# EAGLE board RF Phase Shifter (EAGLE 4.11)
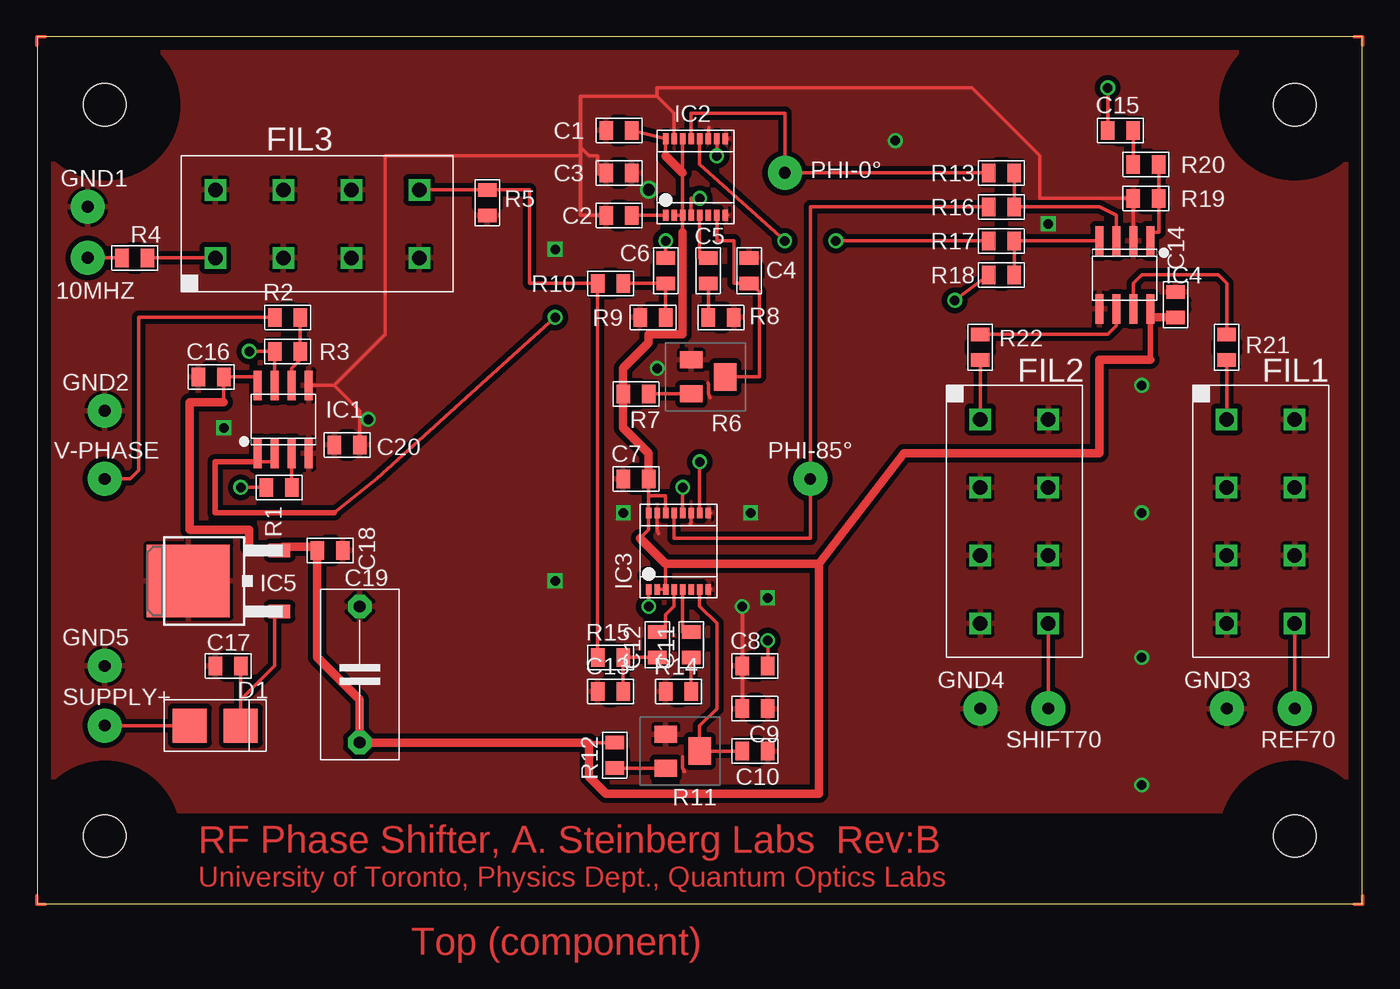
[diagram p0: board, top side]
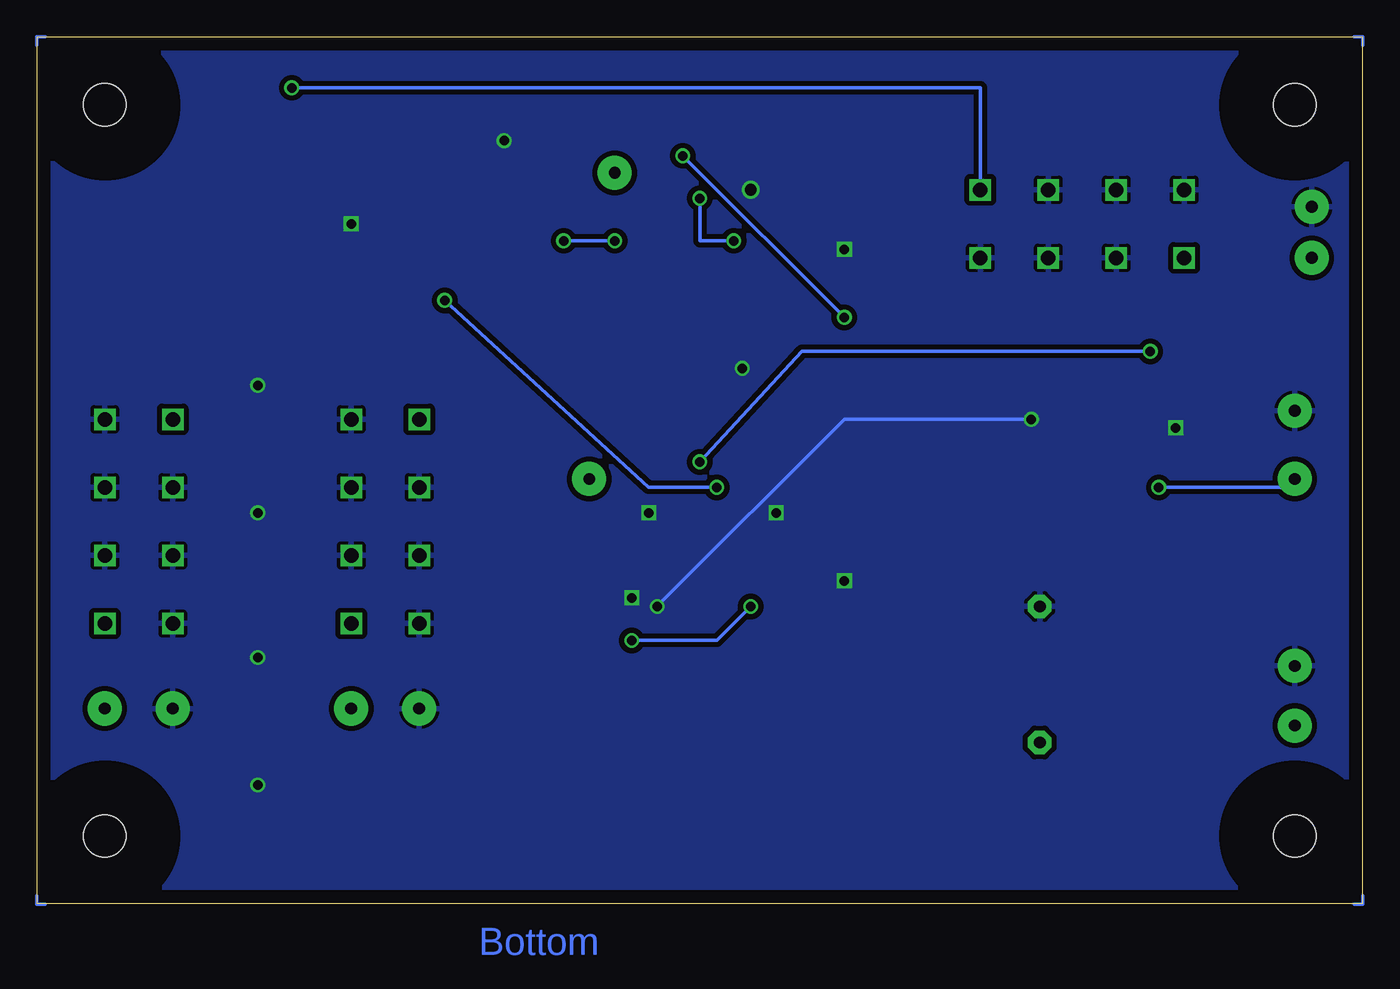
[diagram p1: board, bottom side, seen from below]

Size 99.04 x 64.76 mm. Coordinates in mm from the lower left corner, seen from the top.
Outline: 34.92,0.01 99.04,0.01
Outline: 0,0 99.03,0 99.03,64.76 0,64.76 0,0
Copper layers (1*16): Top 0.035mm / dielectric 1.5mm / Bottom 0.035mm
Design rules "default": minimum track width 10mil, minimum drill 24mil, track to track 12mil, track to pad 10mil, pad to pad 8mil, via to via 10mil, smd to smd 8mil, copper to edge 40mil, drill to drill 8mil, minimum pad ring 10mil, minimum via ring 8mil, stop-mask expansion 4mil, vias tented up to drill 0mil, thermal gap 10mil
Holes 3.17 mm at 5.07,5.08 93.97,5.08 5.07,59.68 93.97,59.68
tKeepout: area -0.2,-0.2 to 10.3,10.3; area 88.7,-0.2 to 99.2,10.3; area -0.2,54.4 to 10.3,64.9; area 88.7,54.4 to 99.2,64.9
tRestrict: area -0.2,54.4 to 10.3,64.9; area 88.7,54.4 to 99.2,64.9; area -0.2,-0.2 to 10.3,10.3; area 88.7,-0.2 to 99.2,10.3
bRestrict: area -0.2,-0.2 to 10.3,10.3; area 88.7,-0.2 to 99.2,10.3; area 88.7,54.4 to 99.2,64.9; area -0.2,54.4 to 10.3,64.9

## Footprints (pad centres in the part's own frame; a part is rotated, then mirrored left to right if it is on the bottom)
TP-HOLE = drill 0.889 pad 2.54 round: P$1 0,0
0805 = smd 1.016 x 1.397: 1 -1.905,0; 2 0,0
PASSIVE_0.4" = drill 0.889 pad 1.778 octagon: 1 -5.08,0; 2 5.08,0
DIODE-SMT = smd 2.54 x 2.54: A -1.27,0; K 2.54,0
A01-MINICIRCUITS = drill 1.067 square: 1 -7.62,-2.54; 2 -7.62,2.54; 3 -2.54,-2.54; 4 -2.54,2.54; 5 2.54,-2.54; 6 2.54,2.54; 7 7.62,-2.54; 8 7.62,2.54
SOIC8 = smd 0.6 x 2.2: 1 -1.905,-2.54; 2 -0.635,-2.54; 3 0.635,-2.54; 4 1.905,-2.54; 5 1.905,2.54; 6 0.635,2.54; 7 -0.635,2.54; 8 -1.905,2.54
QSOP-16(RQ-16) = smd 0.406 x 0.813: 1 -1.27,-3.175; 2 -0.635,-3.175; 3 0,-3.175; 4 0.635,-3.175; 5 1.27,-3.175; 6 1.905,-3.175; 7 2.54,-3.175; 8 3.175,-3.175; 9 3.175,2.54; 10 2.54,2.54; 11 1.905,2.54; 12 1.27,2.54; 13 0.635,2.54; 14 0,2.54; 15 -0.635,2.54; 16 -1.27,2.54
TO252 = smd 1 x 1.6: 1 -2.28,-4.8; 2 2.28,-4.8 | smd 5.4 x 6.2: 3 0,2.02
3214W = smd 1.651 x 1.27: CCW 1.27,-1.27; CW 1.27,1.27 | smd 1.651 x 2.032: W -1.27,0

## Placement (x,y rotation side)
10MHZ  [TP-HOLE]  3.8,48.25 0 top
C1  0.1uF  [0805]  44.44,57.78 0 top
C2  330pF  [0805]  44.44,51.43 0 top
C3  0.1uF  [0805]  42.53,54.6 180 top
C4  0.1uF  [0805]  53.2,46.35 270 top
C5  330pF  [0805]  50.15,48.25 90 top
C6  330pF  [0805]  46.98,48.25 90 top
C7  0.1uF  [0805]  45.71,31.75 0 top
C8  330pF  [0805]  54.6,17.78 0 top
C9  0.1uF  [0805]  52.69,14.6 180 top
C10  0.1uF  [0805]  52.69,11.42 180 top
C11  330pF  [0805]  48.88,20.32 90 top
C12  330pF  [0805]  46.34,20.32 90 top
C13  330pF  [0805]  43.8,15.87 0 top
C14  0.1uF  [0805]  85.08,45.71 90 top
C15  330pF  [0805]  81.9,57.78 0 top
C16  0.1uF  [0805]  13.96,39.36 0 top
C17  0.1uF  [0805]  15.23,17.78 0 top
C18  0.1uF  [0805]  20.94,26.41 180 top
C19  10uF  [PASSIVE_0.4"]  24.12,17.14 270 top
C20  0.1uF  [0805]  24.12,34.28 0 top
D1  1N4004  [DIODE-SMT]  12.69,13.33 0 top
FIL1  PBP-70  [A01-MINICIRCUITS]  91.43,28.57 270 top
FIL2  PBP-70  [A01-MINICIRCUITS]  73.01,28.57 270 top
FIL3  PLP10.7  [A01-MINICIRCUITS]  20.94,50.79 0 top
GND1  [TP-HOLE]  3.8,52.06 0 top
GND2  [TP-HOLE]  5.07,36.82 0 top
GND3  [TP-HOLE]  88.89,14.6 0 top
GND4  [TP-HOLE]  70.47,14.6 0 top
GND5  [TP-HOLE]  5.07,17.78 0 top
IC1  LT1807CS8  [SOIC8]  18.4,36.19 0 top
IC2  AD8330ARQ  [QSOP-16(RQ-16)]  48.25,54.6 0 top
IC3  AD8330ARQ  [QSOP-16(RQ-16)]  46.98,26.67 0 top
IC4  LT1720  [SOIC8]  81.27,46.98 180 top
IC5  7805DT  [TO252]  13.32,24.12 90 top
PHI-0°  [TP-HOLE]  55.87,54.6 90 top
PHI-85°  [TP-HOLE]  57.77,31.75 0 top
R1  2.21K  [0805]  19.04,31.11 0 top
R2  2.21K  [0805]  19.67,43.81 0 top
R3  2.21K  [0805]  17.77,41.27 180 top
R4  49.9  [0805]  8.24,48.25 0 top
R5  64.9  [0805]  33.64,53.34 90 top
R6  10K  [3214W]  50.15,39.36 180 top
R7  2.21K  [0805]  43.8,38.09 180 top
R8  49.9  [0805]  50.15,43.81 180 top
R9  49.9  [0805]  46.98,43.81 0 top
R10  499  [0805]  43.8,46.35 0 top
R11  10K  [3214W]  48.25,11.42 180 top
R12  2.21K  [0805]  43.17,12.06 90 top
R13  221  [0805]  71.11,54.6 180 top
R14  49.9  [0805]  48.88,15.87 0 top
R15  499  [0805]  43.8,18.41 0 top
R16  221  [0805]  73.01,52.06 0 top
R17  221  [0805]  71.11,49.52 180 top
R18  221  [0805]  73.01,46.98 0 top
R19  2.21K  [0805]  83.81,52.7 0 top
R20  499  [0805]  83.81,55.24 0 top
R21  49.9  [0805]  88.89,40.63 270 top
R22  49.9  [0805]  70.47,40.63 270 top
REF70  [TP-HOLE]  93.97,14.6 0 top
SHIFT70  [TP-HOLE]  75.55,14.6 0 top
SUPPLY+  [TP-HOLE]  5.07,13.33 0 top
U$26  [TARGET]  not placed on the board
U$27  [TARGET]  not placed on the board
U$28  [TARGET]  not placed on the board
U$29  [TITLEBLOCK_PCB]  not placed on the board
V-PHASE  [TP-HOLE]  5.07,31.75 0 top

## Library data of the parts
10MHZ C1-C20 D1 FIL1-FIL3 GND1-GND5 IC1-IC5 PHI-0° PHI-85° R1-R22 REF70 SHIFT70 SUPPLY+ U$26-U$29 V-PHASE = 0-UofT-Physics

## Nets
+2.5V: C1.1 C2.1 C3.1 C3.2 C4.1 C7.1 C8.1 C9.1 C9.2 C10.1 C13.1 C14.2 C16.1 C17.1 C18.1 C19.1 C20.1 C20.2 FIL1.2 FIL1.3 FIL1.4 FIL1.5 FIL1.6 FIL1.7 FIL2.2 FIL2.3 FIL2.4 FIL2.5 FIL2.6 FIL2.7 FIL3.2 FIL3.3 FIL3.4 FIL3.5 FIL3.6 FIL3.7 GND1.P$1 GND2.P$1 GND3.P$1 GND4.P$1 GND5.P$1 IC1.4 IC1.5 IC2.8 IC2.9 IC2.11 IC2.15 IC3.8 IC3.9 IC3.11 IC3.15 IC4.2 IC4.5 IC5.3 R5.1 R6.CCW R8.1 R9.1 R11.CCW R14.1 R19.1
+5V: C1.2 C7.2 C14.1 C16.2 C18.2 C19.2 IC1.8 IC2.2 IC2.3 IC2.14 IC2.16 IC3.2 IC3.3 IC3.14 IC3.16 IC4.8 IC5.2 R7.2 R12.2
N$1: IC1.1 IC1.2 IC2.10
N$2: IC1.3 R1.2
N$3: R1.1 R2.1 V-PHASE.P$1
N$4: D1.A SUPPLY+.P$1
N$5: IC1.7 IC3.10 R3.2
N$6: C12.1 C13.2 R15.2
N$7: 10MHZ.P$1 R4.1
N$8: IC1.6 R2.2 R3.1
N$9: FIL3.1 R4.2
N$10: R11.CW R12.1
N$11: IC2.12 R17.2
N$12: C2.2 IC2.1
N$13: C4.2 IC2.7 R6.W
N$14: R6.CW R7.1
N$15: IC2.13 PHI-0°.P$1 R13.2
N$16: C6.1 R9.2 R10.2
N$17: C5.1 R8.2
N$18: C5.2 IC2.5
N$19: C6.2 IC2.4
N$20: IC4.4 R17.1 R18.2
N$21: IC4.3 R13.1 R16.2
N$22: C8.2 IC3.1
N$23: C10.2 IC3.7 R11.W
N$24: IC3.12 R18.1
N$25: C11.1 R14.2
N$26: C11.2 IC3.5
N$27: C12.2 IC3.4
N$29: IC3.13 PHI-85°.P$1 R16.1
N$30: IC4.7 R21.1
N$31: IC4.1 R19.2 R20.2
N$32: C15.2 R20.1
N$33: FIL2.1 R22.2
N$34: FIL1.1 R21.2
N$35: IC4.6 R22.1
N$36: FIL1.8 REF70.P$1
N$37: FIL2.8 SHIFT70.P$1
N$38: C15.1 FIL3.8 R5.2 R10.1 R15.1
N$39: C17.2 D1.K IC5.1

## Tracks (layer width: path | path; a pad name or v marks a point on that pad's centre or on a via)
+2.5V  (via drill 0.71, 0.89)
  Top 0.254: IC4.2 R19.1 74.92,52.7 74.92,55.88 69.84,60.95 46.34,60.95 46.34,60.32 | C9.2 C8.1 v52.69,22.22 | IC2.15 47.61,59.05 46.34,60.32 | 46.34,60.32 40.63,60.32 40.63,56.51 | 40.63,56.51 41.26,55.88 41.9,55.88 41.9,54.6 42.53,53.97 C3.2 | C2.1 40.63,51.43 40.63,55.88 | 40.63,55.88 40.63,56.51 | 24.12,36.19 24.12,36.82 22.21,38.73 | 22.21,38.73 IC1.5 | C20.2 24.12,36.19 | 24.12,36.19 v24.75,36.19 | 40.63,55.88 26.02,55.88 26.02,42.54 22.21,38.73 | IC3.15 46.34,27.94 46.42,27.64 | 50.18,23.49 IC3.8 50.3,23.49 | 48.25,10.15 48.25,10.79 48.23,11 | 48.25,10.15 48.26,10.15 | 50.18,29.2 IC3.9 50.3,29.2 | 51.45,51.43 IC2.8 51.57,51.43 | IC2.11 50.15,57.78 50.22,58.01 | 51.45,57.14 IC2.9 51.57,57.14 | 50.15,38.09 50.15,38.73 50.14,38.95 | 50.15,38.09 50.17,38.09 | 48.39,9.89 48.25,10.15 | 50.29,37.83 50.15,38.09 | IC3.11 48.88,28.57 48.82,28.34
  Bottom 0.254: v52.69,22.22 38.72,36.19 v24.75,36.19
  other vias: 46.34,40 45.71,53.34 64.12,57.02 82.54,38.73 82.54,29.21 82.54,18.41 82.54,8.88 43.8,29.21 53.33,29.21 54.6,22.86 38.72,24.12 13.96,35.55 38.72,48.89 75.55,50.79
  pour Bottom (isolate 0.381): 0.62,0.5 98.41,0.5 98.41,64.13 0.62,64.13
  pour Top (isolate 0.381): 0.62,6.98 98.41,6.98 98.41,64.13 0.62,64.13
+5V
  Top 0.254: IC1.8 16.5,39.36 C16.2 13.96,37.46 | 15.86,26.67 17.77,26.67 IC5.2 18.4,26.67 | 41.26,12.06 R12.2 | C1.2 IC2.16 46.98,55.88 | IC2.3 IC2.2 | IC2.3 48.25,54.6 IC2.14 | IC3.2 IC3.3 46.98,25.39 | 45.07,27.3 45.71,27.94 IC3.16 45.71,30.48 | 48.25,50.16 IC2.3 | IC3.14 46.98,30.48 45.71,30.48 | 45.71,30.48 C7.2 | C18.2 20.94,26.67 | 83.17,43.81 IC4.8
  Top 0.406: 83.17,40.63 83.17,43.81
  Top 0.635: 48.25,54.6 46.98,55.88 | 45.07,27.3 46.98,25.39 58.41,25.39 | 58.41,25.39 64.76,33.65 79.36,33.65 79.36,40.63 83.17,40.63 | 58.41,25.39 58.41,8.25 42.53,8.25 41.26,9.52 41.26,12.06 C19.2 24.12,15.23 20.94,18.41 C18.2 | C7.2 45.71,33.65 43.8,35.55 R7.2 43.8,40 45.71,41.9 45.71,42.54 48.25,42.54 48.25,50.16 | 20.94,26.67 18.4,26.67 | 15.86,26.67 15.86,27.94 11.42,27.94 11.42,37.46 13.96,37.46 | 83.17,43.81 C14.1
N$1  (via drill 0.71)
  Top 0.254: v50.79,55.88 IC2.10 | v38.72,43.81 25.39,31.75 22.21,29.21 | IC1.2 17.77,33.02 16.5,33.02 IC1.1
  Top 0.406: 22.21,29.21 13.32,29.21 13.32,33.02 16.5,33.02
  Bottom 0.254: v38.72,43.81 v50.79,55.88
N$2
  Top 0.254: R1.2 IC1.3
N$3  (via drill 0.71)
  Top 0.254: v15.23,31.11 R1.1 | R2.1 7.61,43.81 7.61,32.38 6.97,31.75 V-PHASE.P$1
  Bottom 0.254: v15.23,31.11 5.7,31.11 V-PHASE.P$1
N$4
  Top 0.254: SUPPLY+.P$1 D1.A
N$5  (via drill 0.71)
  Top 0.254: v49.52,33.02 IC3.10 | v15.86,41.27 R3.2 IC1.7
  Bottom 0.254: v49.52,33.02 41.9,41.27 v15.86,41.27
N$6
  Top 0.254: C13.2 R15.2 C12.1
N$7
  Top 0.254: 10MHZ.P$1 R4.1
N$8
  Top 0.254: R2.2 R3.1 19.67,40.63 19.04,40 IC1.6
N$9
  Top 0.254: R4.2 FIL3.1
N$10
  Top 0.254: R12.1 R11.CW
N$11  (via drill 0.71)
  Top 0.254: IC2.12 49.52,55.24 v55.87,49.52 | v59.68,49.52 R17.2
  Bottom 0.254: v55.87,49.52 v59.68,49.52
N$12
  Top 0.254: C2.2 IC2.1
N$13
  Top 0.254: 52.06,40 R6.W 53.96,39.36 53.96,45.71 53.33,46.35 C4.2 52.06,46.35 52.06,49.52 50.79,49.52 IC2.7
N$14
  Top 0.254: R7.1 R6.CW
N$15
  Top 0.254: IC2.13 48.88,59.05 55.87,59.05 PHI-0°.P$1 R13.2
N$16
  Top 0.254: R10.2 C6.1 R9.2
N$17
  Top 0.254: R8.2 C5.1
N$18
  Top 0.254: IC2.5 49.52,48.25 C5.2
N$19  (via drill 0.71)
  Top 0.254: IC2.4 48.88,52.7 v49.52,52.7 | C6.2 v46.98,49.52
  Bottom 0.254: v49.52,52.7 49.52,49.52 v46.98,49.52
N$20
  Top 0.254: R18.2 R17.1 IC4.4
N$21
  Top 0.254: R13.1 R16.2 79.36,52.06 80.63,51.43 IC4.3
N$22  (via drill 0.71)
  Top 0.254: v45.71,22.22 IC3.1 | v54.6,19.68 C8.2
  Bottom 0.254: v45.71,22.22 48.25,19.68 v54.6,19.68
N$23
  Top 0.254: IC3.7 49.52,22.22 50.79,20.95 50.79,14.6 49.52,13.33 R11.W C10.2
N$24  (via drill 0.71)
  Top 0.254: IC3.12 v48.25,31.11 | v68.57,45.08 R18.1
  Bottom 0.254: v48.25,31.11 53.33,31.11 v68.57,45.08
N$25
  Top 0.254: R14.2 C11.1
N$26
  Top 0.254: IC3.5 48.25,20.32 C11.2
N$27
  Top 0.254: IC3.4 47.61,22.22 46.98,21.59 46.98,20.32 C12.2
N$28
  Bottom 0.254: -0.01,0.63 -0.01,-0.01 0.62,-0.01
N$29
  Top 0.254: IC3.13 47.61,27.3 57.77,27.3 PHI-85°.P$1 57.77,52.06 R16.1
N$30
  Top 0.254: R21.1 88.89,46.35 88.25,46.98 82.54,46.98 81.9,46.35 IC4.7
N$31
  Top 0.254: IC4.1 83.17,50.16 83.81,50.16 R19.2 R20.2
N$32
  Top 0.254: R20.1 C15.2
N$33
  Top 0.254: FIL2.1 R22.2
N$34
  Top 0.254: FIL1.1 R21.2
N$35
  Top 0.254: R22.1 80,42.54 80.63,43.17 IC4.6
N$36
  Top 0.254: REF70.P$1 FIL1.8
N$37
  Top 0.254: SHIFT70.P$1 FIL2.8
N$38  (via drill 0.71)
  Top 0.254: R15.1 R10.1 36.82,46.35 36.82,53.34 R5.2 FIL3.8 | v80,60.95 C15.1
  Bottom 0.254: v80,60.95 28.56,60.95 FIL3.8
N$39
  Top 0.254: 15.23,15.23 C17.2 | D1.K 15.23,15.23 | 15.23,15.23 17.77,17.78 17.77,21.59 IC5.1
N$40
  Top 0.254: -0.01,0.63 -0.01,-0.01 0.62,-0.01
N$41
  Bottom 0.254: 98.41,-0.01 99.05,-0.01 99.05,0.63
N$42
  Top 0.254: 98.41,-0.01 99.05,-0.01 99.05,0.63
N$43
  Bottom 0.254: 99.05,64.13 99.05,64.77 98.41,64.77
N$44
  Top 0.254: 99.05,64.13 99.05,64.77 98.41,64.77
N$45
  Bottom 0.254: 0.62,64.77 -0.01,64.77 -0.01,64.13
N$46
  Top 0.254: 0.62,64.77 -0.01,64.77 -0.01,64.13

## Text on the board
Top: RF Phase Shifter, A. Steinberg Labs Rev:B | University of Toronto, Physics Dept., Quantum Optics Labs | Top (component)
Bottom: Bottom
Target: RF Phase Shifter | A. Steinberg Labs | Alan Stummer Dec'03 | B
